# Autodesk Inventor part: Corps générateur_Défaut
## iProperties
Shininess: 64.0
Length Units: 11269
Angle Units: 11279
Time Units: 11290
Mass Units: 11283
Length Display Precision: 3
Angle Display Precision: 2
Compacted: True
Part Number: Corps générateur_Défaut
Document SubType Name: Modeling
Created: 2006-01
Material: Par défaut
Designer: riri
Density: 0.0
Volumn: 0.0
Area: 0.0
PropertySet Name: Model Information
Control State: 0
Master: False
Checked Out: False
Author: riri
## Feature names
1. Base1
